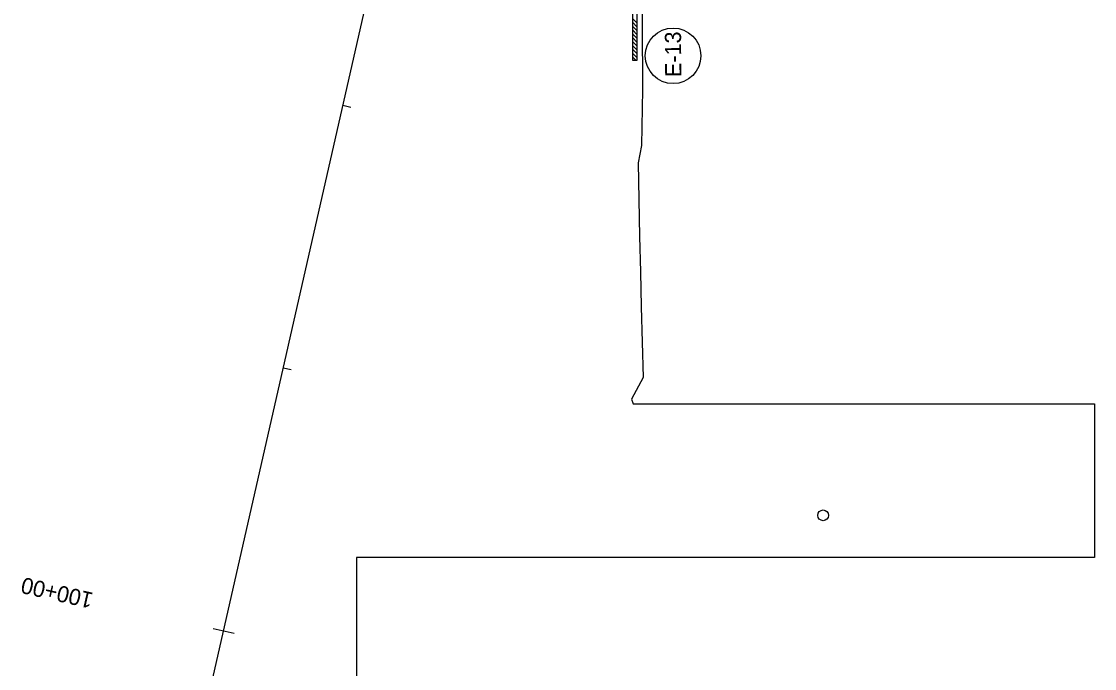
# Model space of a CAD drawing. Extents: x 1710760 to 1713003, y 548603 to 551142.
# Drawn here: x 1712237.1 to 1712635.8, y 549901.4 to 550141.7 of the extents above; entities that cross this region are included whole.
import ezdxf

# ---------------------------------------------------------------- set-up
doc = ezdxf.new("R2010")
doc.units = 0
for name, color, linetype in [('R_Erosion', 7, 'Continuous'), ('R_Erosion_STG 2', 7, 'Continuous'), ('R_Horz Alg', 7, 'Continuous'), ('R_Horz Alg Annot', 7, 'Continuous'), ('R_No Plot', 7, 'Continuous')]:
    doc.layers.add(name, color=color, linetype=linetype)

msp = doc.modelspace()

# ---------------------------------------------------------------- linework, layer by layer
at = {"layer": 'R_Erosion'}
for p, q in [((1712465.73, 550141.21), (1712464.22, 550142.73)), ((1712465.73, 550139.78), (1712464.23, 550141.3)), ((1712465.74, 550138.35), (1712464.23, 550139.88)), ((1712465.75, 550136.92), (1712464.24, 550138.45)), ((1712465.75, 550135.49), (1712464.25, 550137.02)), ((1712465.76, 550134.07), (1712464.25, 550135.59)), ((1712465.77, 550132.64), (1712464.26, 550134.16)), ((1712465.77, 550131.21), (1712464.27, 550132.73)), ((1712465.78, 550129.78), (1712464.27, 550131.3)), ((1712465.79, 550128.35), (1712464.28, 550129.87)), ((1712465.48, 550127.24), (1712464.29, 550128.45)), ((1712465.79, 550127.24), (1712464.29, 550127.23))]:
    msp.add_line(p, q, dxfattribs=at)
for points in [[(1712464.29, 550127.23), (1712464.23, 550141.11), (1712464.11, 550165.8), (1712464.36, 550181.72), (1712464.61, 550197.61), (1712464.86, 550213.49), (1712465.11, 550229.35), (1712465.14, 550245.45), (1712465.17, 550261.57), (1712465.2, 550277.69), (1712465.23, 550293.84), (1712465.48, 550310.36), (1712465.74, 550326.86), (1712465.99, 550343.35), (1712466.25, 550359.84), (1712466.43, 550376.03), (1712466.62, 550392.23), (1712466.8, 550408.42), (1712466.89, 550453.35)], [(1712468.39, 550453.34), (1712468.3, 550408.41), (1712468.11, 550392.22), (1712467.93, 550376.02), (1712467.75, 550359.82), (1712467.49, 550343.33), (1712467.24, 550326.83), (1712466.98, 550310.34), (1712466.73, 550293.83), (1712466.7, 550277.69), (1712466.67, 550261.57), (1712466.64, 550245.44), (1712466.61, 550229.34), (1712466.36, 550213.47), (1712466.11, 550197.58), (1712465.86, 550181.7), (1712465.61, 550165.8), (1712465.73, 550141.11), (1712465.79, 550127.24)]]:
    msp.add_lwpolyline(points, dxfattribs=at)
at = {"layer": 'R_Erosion_STG 2'}
msp.add_circle((1712479.23, 550128.98), 10.32, dxfattribs=at)
at = {"layer": 'R_Horz Alg'}
msp.add_line((1712246.77, 549627.28), (1712450.81, 550525.82), dxfattribs=at)
at = {"layer": 'R_Horz Alg Annot'}
for points in [[(1712359.42, 550109.8), (1712356.49, 550110.47)], [(1712337.27, 550012.29), (1712334.35, 550012.95)], [(1712308.3, 549916.32), (1712316.11, 549914.55)]]:
    msp.add_lwpolyline(points, dxfattribs=at)
msp.add_circle((1712534.97, 549958.28), 2, dxfattribs=at)
at = {"layer": 'R_No Plot'}
for p, q in [((1712464.35, 549999.67), (1712635.83, 549999.67)), ((1712635.83, 549999.67), (1712635.83, 549942.65))]:
    msp.add_line(p, q, dxfattribs=at)
for points in [[(1712467.61, 550165.79), (1712467.73, 550141.12), (1712467.84, 550116.46), (1712467.53, 550095.6), (1712466.2, 550089.23), (1712466.46, 550075.55), (1712466.71, 550061.86), (1712467.06, 550048.77), (1712467.41, 550035.68), (1712467.77, 550022.58), (1712468.12, 550009.49), (1712463.76, 550001.4), (1712464.35, 549999.67)], [(1712635.83, 549942.65), (1712361.6, 549942.65), (1712361.6, 549562.59)]]:
    msp.add_lwpolyline(points, dxfattribs=at)

# ---------------------------------------------------------------- texts
at = {"layer": 'R_Erosion_STG 2'}
msp.add_text('E-13', height=5.999, rotation=90.4005, dxfattribs=at).set_placement((1712482.29, 550121.09))
at = {"layer": 'R_Horz Alg Annot'}
msp.add_text('100+00', height=6, rotation=167.2066, dxfattribs=at).set_placement((1712264.11, 549929.43))

doc.saveas('drawing.dxf')
